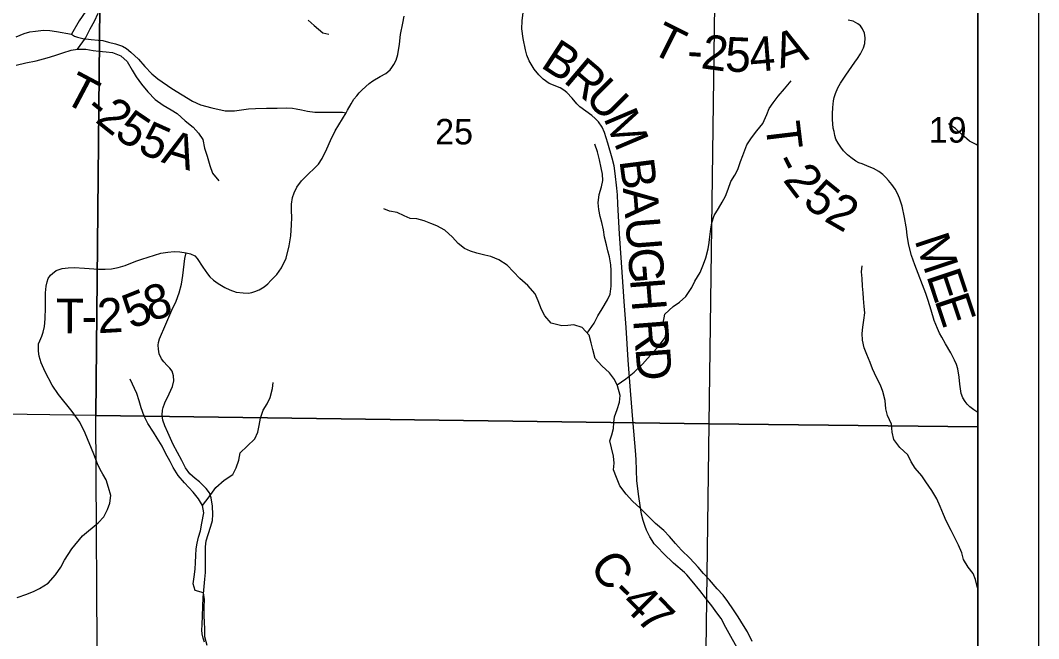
# Model space of a CAD drawing. Extents: x 0 to 34, y -8.9 to 22.
# Drawn here: x 28.944 to 30.617, y 17.37 to 18.385 of the extents above; entities that cross this region are included whole.
import ezdxf

# ---------------------------------------------------------------- set-up
doc = ezdxf.new("R2010")
doc.units = 0
for name, color, linetype in [('GM_X_Corporation', 7, 'Continuous'), ('GM_X_County_Road', 7, 'Continuous'), ('GM_X_County_Road_Text', 7, 'Continuous'), ('GM_X_Minor_River', 7, 'Continuous'), ('GM_X_Section_Text', 7, 'Continuous'), ('GM_X_Township_Road', 7, 'Continuous'), ('GM_X_Township_Road_Text', 7, 'Continuous'), ('SH_Data', 7, 'Continuous')]:
    doc.layers.add(name, color=color, linetype=linetype)

msp = doc.modelspace()

# ---------------------------------------------------------------- linework, layer by layer
at = {"layer": 'GM_X_Corporation'}
msp.add_lwpolyline([(28.3182, 16.8002), (29.5528, 16.7835), (30.4571, 16.7673), (30.5167, 16.7663), (30.5167, 21.4), (23.7167, 21.4)], dxfattribs=at)
for points in [[(30.5167, 16.7663), (30.5167, 21.4), (28.2203, 21.4), (28.2198, 21.3092), (28.2124, 18.7899), (28.2124, 18.7889), (28.2011, 18.1006), (28.201, 18.0921), (28.1882, 17.3108), (28.1928, 16.8054), (28.3182, 16.8002), (29.5528, 16.7835), (30.4571, 16.7673)], [(29.0775, 18.7458), (29.0677, 17.7366), (28.2008, 17.7487), (28.2049, 18.3054), (28.2083, 18.7401)], [(30.0887, 18.7357), (30.0751, 17.7225), (29.0677, 17.7366), (29.0775, 18.7458)], [(30.5167, 17.7179), (30.5167, 18.7296), (30.0887, 18.7357), (30.0751, 17.7225)], [(30.0751, 17.7225), (30.0622, 16.7735), (29.0733, 16.7902), (29.0677, 17.7366)], [(30.5167, 16.7657), (30.5167, 17.7179), (30.0751, 17.7225), (30.0622, 16.7735)]]:
    msp.add_lwpolyline(points, close=True, dxfattribs=at)
at = {"layer": 'GM_X_County_Road'}
msp.add_lwpolyline([(30.1266, 17.3451), (30.1026, 17.3879), (30.095, 17.4027), (30.0894, 17.4102), (30.0852, 17.4163), (30.0796, 17.4237), (30.0756, 17.4292), (30.0694, 17.4369), (30.0599, 17.449), (30.0477, 17.4641), (30.0388, 17.4747), (30.0351, 17.4784), (30.017, 17.494), (30.0002, 17.5097), (29.9911, 17.5195), (29.9853, 17.5258), (29.9817, 17.531), (29.978, 17.5371), (29.9757, 17.5413), (29.9725, 17.548), (29.97, 17.5541), (29.967, 17.5637), (29.9644, 17.5745), (29.962, 17.5883), (29.9598, 17.6032), (29.9565, 17.629), (29.9552, 17.6642), (29.9545, 17.6788), (29.9503, 17.7232), (29.9459, 17.7772), (29.9425, 17.8272), (29.9392, 17.8808), (29.9357, 17.9239), (29.9346, 17.9403), (29.9312, 17.9875), (29.9282, 18.0348), (29.9254, 18.0833), (29.9247, 18.0989), (29.9238, 18.11), (29.9211, 18.134), (29.9192, 18.1467), (29.9162, 18.1589), (29.9091, 18.1836), (29.9035, 18.201), (29.8994, 18.21), (29.8936, 18.2188), (29.8883, 18.2244), (29.8826, 18.2291), (29.8728, 18.2364), (29.8631, 18.2432), (29.858, 18.2485), (29.8502, 18.2578), (29.8416, 18.2669), (29.8365, 18.2706), (29.8304, 18.2745), (29.8126, 18.282), (29.8028, 18.2887), (29.7954, 18.2959), (29.7879, 18.3054), (29.7799, 18.3192), (29.7761, 18.3281), (29.7736, 18.3372), (29.7698, 18.3557), (29.7676, 18.3715), (29.768, 18.3849), (29.7704, 18.4027)], dxfattribs=at)
at = {"layer": 'GM_X_Minor_River'}
for points in [[(29.0376, 18.3379), (29.0506, 18.3563), (29.0584, 18.3716), (29.0654, 18.3842), (29.0717, 18.3972)], [(29.4167, 18.3857), (29.4263, 18.3771), (29.4405, 18.3648), (29.4508, 18.363)], [(28.937, 18.3119), (28.9529, 18.3159), (28.9695, 18.3192), (28.9816, 18.322), (28.9915, 18.3248), (29.0039, 18.3291), (29.0138, 18.3323), (29.0274, 18.3367), (29.0376, 18.3379), (29.0512, 18.3381), (29.0634, 18.336), (29.0729, 18.335), (29.0847, 18.334), (29.0953, 18.3326), (29.1087, 18.3271), (29.119, 18.3181), (29.1272, 18.3034), (29.1338, 18.2929), (29.1427, 18.2804), (29.1531, 18.268), (29.165, 18.2553), (29.1784, 18.2463), (29.1914, 18.2385), (29.2014, 18.2322), (29.2144, 18.2206), (29.2278, 18.2098), (29.2367, 18.2), (29.2433, 18.1895), (29.2461, 18.1755), (29.2508, 18.1622), (29.2552, 18.1471), (29.2592, 18.1342), (29.2696, 18.1218)], [(29.9241, 17.7865), (29.9386, 17.7967), (29.9521, 17.8075), (29.9656, 17.8206), (29.9742, 17.8302), (29.9843, 17.8413), (29.9936, 17.8517), (30.0033, 17.8644), (30.0051, 17.8758), (29.9996, 17.8882), (30.0028, 17.9027), (30.0163, 17.9154), (30.0265, 17.9224), (30.037, 17.9316), (30.047, 17.9466), (30.0518, 17.9569), (30.0607, 17.9714), (30.0659, 17.9852), (30.0699, 17.9955), (30.0735, 18.0099), (30.0753, 18.0206), (30.0767, 18.0301), (30.0784, 18.043), (30.0798, 18.0529), (30.0834, 18.0651), (30.0908, 18.0766), (30.0968, 18.0866), (30.102, 18.0969), (30.1068, 18.108), (30.1111, 18.1209), (30.1178, 18.1309), (30.1223, 18.1404), (30.1266, 18.1534), (30.1307, 18.1637), (30.1373, 18.1809), (30.1447, 18.1927), (30.1537, 18.2042), (30.1638, 18.2161), (30.17, 18.2306), (30.1741, 18.2406), (30.1808, 18.2502), (30.189, 18.2609), (30.1991, 18.2728), (30.2103, 18.2862)], [(30.5167, 18.1801), (30.514, 18.1815), (30.5033, 18.1871), (30.4903, 18.1979), (30.4803, 18.2077), (30.4684, 18.2155)], [(29.8751, 17.8716), (29.8865, 17.8883), (29.8925, 17.9002), (29.8995, 17.9116), (29.9084, 17.9262), (29.9125, 17.9357), (29.9142, 17.9487), (29.9144, 17.9627), (29.9142, 17.9745), (29.9137, 17.984), (29.9117, 17.9968), (29.9089, 18.0067), (29.9065, 18.0169), (29.9037, 18.0294), (29.9016, 18.0411), (29.8992, 18.0536), (29.8964, 18.0635), (29.894, 18.0745), (29.8931, 18.0858), (29.8948, 18.0992), (29.8984, 18.1121), (29.9005, 18.1224), (29.9004, 18.133), (29.898, 18.1432), (29.8952, 18.1565), (29.8919, 18.1697), (29.8876, 18.1822)], [(29.7776, 17.9499), (29.7645, 17.9615), (29.7538, 17.9724), (29.7434, 17.9833), (29.73, 17.9922), (29.7166, 17.9974), (29.7068, 17.9999), (29.6938, 18.0032), (29.6831, 18.0064), (29.6736, 18.0109), (29.6629, 18.0191), (29.6536, 18.0292), (29.6413, 18.0408), (29.628, 18.0479), (29.618, 18.0519), (29.6074, 18.056), (29.5952, 18.0592), (29.5842, 18.0598), (29.5743, 18.0643), (29.5628, 18.0698), (29.5502, 18.0723), (29.5407, 18.0756)], [(30.5167, 17.4524), (30.5164, 17.4532), (30.5128, 17.4669), (30.5089, 17.4767), (30.5008, 17.4872), (30.4934, 17.5), (30.4906, 17.5106), (30.4851, 17.5231), (30.4727, 17.5472), (30.4645, 17.5635), (30.4606, 17.5737), (30.4547, 17.5869), (30.4492, 17.5997), (30.4411, 17.6129), (30.4314, 17.6272), (30.4248, 17.6374), (30.414, 17.6498), (30.4074, 17.6603), (30.4016, 17.672), (30.3889, 17.684), (30.3789, 17.6972), (30.3761, 17.7089), (30.3748, 17.7222), (30.3685, 17.7365), (30.3657, 17.7475), (30.3644, 17.7612), (30.3608, 17.7759), (30.3568, 17.7861), (30.3502, 17.7989), (30.344, 17.8129), (30.34, 17.8235), (30.3342, 17.8367), (30.3299, 17.8473), (30.3274, 17.8602), (30.3269, 17.8712), (30.3279, 17.8814), (30.3296, 17.8932), (30.331, 17.905), (30.3301, 17.9156), (30.3288, 17.9285), (30.3283, 17.938), (30.3274, 17.949), (30.3265, 17.9612), (30.3259, 17.9725), (30.3269, 17.9824)], [(30.1461, 17.3653), (30.1383, 17.3812), (30.1317, 17.3914), (30.1228, 17.4057), (30.1151, 17.4174), (30.1062, 17.4309), (30.0984, 17.4414), (30.0884, 17.4519), (30.0757, 17.4666), (30.0661, 17.4767), (30.0572, 17.4872), (30.0434, 17.5019), (30.0299, 17.515), (30.0203, 17.5259), (30.0103, 17.5375), (30.0007, 17.5476), (29.9872, 17.5592), (29.9753, 17.5712), (29.9622, 17.584), (29.9492, 17.5956), (29.9392, 17.6072), (29.9288, 17.6208), (29.9229, 17.6347), (29.9182, 17.6472), (29.9192, 17.6582), (29.9182, 17.6696), (29.915, 17.6832), (29.9122, 17.695), (29.9155, 17.7045), (29.918, 17.7152), (29.9187, 17.7247), (29.9201, 17.7342), (29.9241, 17.746), (29.9281, 17.7582), (29.9291, 17.7692), (29.9247, 17.7851), (29.92, 17.7953), (29.9115, 17.8062), (29.8992, 17.8178), (29.8881, 17.8298), (29.8845, 17.845), (29.8817, 17.8556), (29.8781, 17.8685), (29.8665, 17.8808), (29.8532, 17.8852), (29.843, 17.8843), (29.8335, 17.8838), (29.816, 17.8882), (29.8056, 17.9002), (29.8001, 17.9107), (29.7942, 17.9247), (29.7895, 17.9364), (29.7776, 17.9499)], [(29.2504, 17.3584), (29.2468, 17.3727), (29.247, 17.386), (29.2465, 17.397), (29.246, 17.4073), (29.2458, 17.421), (29.2464, 17.4339), (29.2447, 17.4452), (29.231, 17.4489), (29.2274, 17.4598), (29.2292, 17.4712), (29.2309, 17.4838), (29.2315, 17.4948), (29.2318, 17.5062), (29.2328, 17.5172), (29.2342, 17.5267), (29.2363, 17.5363), (29.2396, 17.5469), (29.2421, 17.5595), (29.2453, 17.5766), (29.2428, 17.5888), (29.2366, 17.5997), (29.2274, 17.6106), (29.2135, 17.6256), (29.2031, 17.6376), (29.1946, 17.6508), (29.1899, 17.6606), (29.1821, 17.6745), (29.177, 17.6859), (29.1685, 17.699), (29.1623, 17.7088), (29.1534, 17.7235), (29.1472, 17.7352), (29.1421, 17.7492), (29.1389, 17.7602), (29.1353, 17.7723), (29.1244, 17.7961)], [(29.2429, 17.5884), (29.254, 17.6026), (29.2648, 17.6183), (29.2787, 17.6302), (29.2926, 17.6395), (29.2982, 17.6506), (29.3026, 17.6632), (29.3051, 17.675), (29.3163, 17.6862), (29.329, 17.6981), (29.3338, 17.7092), (29.336, 17.7198), (29.3381, 17.732), (29.3428, 17.745), (29.3491, 17.7553), (29.3539, 17.766), (29.3579, 17.7805), (29.3593, 17.7904)]]:
    msp.add_lwpolyline(points, dxfattribs=at)
at = {"layer": 'GM_X_Township_Road'}
for points in [[(29.0514, 18.4006), (29.0404, 18.3848), (29.0279, 18.3626)], [(29.2463, 17.3639), (29.2439, 17.3706), (29.2424, 17.3776), (29.2419, 17.3839), (29.2427, 17.3923), (29.2442, 17.4372), (29.2468, 17.4673), (29.2477, 17.4783), (29.2479, 17.5006), (29.2477, 17.5207), (29.2491, 17.5304), (29.2521, 17.5408), (29.2567, 17.5545), (29.2592, 17.564), (29.2601, 17.5735), (29.2593, 17.5877), (29.257, 17.6009), (29.2544, 17.6093), (29.2492, 17.6167), (29.2438, 17.622), (29.238, 17.6272), (29.2308, 17.633), (29.2223, 17.6407), (29.2152, 17.6503), (29.2091, 17.6626), (29.1949, 17.6889), (29.1858, 17.7084), (29.1811, 17.7195), (29.1781, 17.7289), (29.1765, 17.7371), (29.1771, 17.7449), (29.1784, 17.7496), (29.1809, 17.7572), (29.1884, 17.7719), (29.1939, 17.784), (29.196, 17.7933), (29.1953, 17.8016), (29.1934, 17.809), (29.1895, 17.8143), (29.185, 17.8186), (29.1795, 17.8244), (29.1757, 17.8296), (29.172, 17.8376), (29.1712, 17.8414), (29.1705, 17.8451), (29.1701, 17.8518), (29.1709, 17.8562), (29.1721, 17.8624), (29.1825, 17.8864), (29.1927, 17.9092), (29.1996, 17.9242), (29.2045, 17.938), (29.2085, 17.9519), (29.2109, 17.9662), (29.2138, 17.9941), (29.2163, 18.0038), (29.2233, 18.0021), (29.2302, 17.9984), (29.2344, 17.9941), (29.2436, 17.9799), (29.251, 17.9692), (29.2548, 17.9642), (29.2613, 17.9588), (29.2688, 17.9531), (29.2795, 17.9468), (29.2877, 17.9427), (29.2981, 17.9392), (29.3097, 17.9377), (29.3185, 17.9375), (29.3238, 17.9384), (29.3289, 17.94), (29.3362, 17.9428), (29.3444, 17.9477), (29.3502, 17.9528), (29.3555, 17.9579), (29.3652, 17.9681), (29.373, 17.9789), (29.3806, 17.995), (29.3852, 18.015), (29.3879, 18.0316), (29.3893, 18.0494), (29.3896, 18.0615), (29.3892, 18.0732), (29.3892, 18.0837), (29.391, 18.0945), (29.3934, 18.102), (29.3979, 18.1115), (29.4058, 18.122), (29.4171, 18.1336), (29.4263, 18.1423), (29.4335, 18.1494), (29.4397, 18.1584), (29.4472, 18.1742), (29.4535, 18.188), (29.4612, 18.2039), (29.4792, 18.2338), (29.4811, 18.2382), (29.4872, 18.2486), (29.4918, 18.2558), (29.4967, 18.2617), (29.5004, 18.2664), (29.5045, 18.2706), (29.5111, 18.277), (29.5168, 18.2817), (29.5229, 18.2859), (29.5347, 18.2931), (29.5441, 18.2982), (29.5512, 18.3041), (29.5542, 18.3079), (29.5573, 18.313), (29.561, 18.3201), (29.5637, 18.3293), (29.5667, 18.3466), (29.5684, 18.3621), (29.5719, 18.3807), (29.5744, 18.3921)], [(30.399, 18.0465), (30.3965, 18.0614), (30.3924, 18.0802), (30.388, 18.0935), (30.3847, 18.1013), (30.3809, 18.1081), (30.3757, 18.1156), (30.3702, 18.1225), (30.3657, 18.1271), (30.3607, 18.1321), (30.354, 18.1373), (30.3452, 18.1419), (30.338, 18.145), (30.3267, 18.1496), (30.3215, 18.1515), (30.3163, 18.1544), (30.3079, 18.1601), (30.3027, 18.1643), (30.2963, 18.1711), (30.2918, 18.1769), (30.2873, 18.1836), (30.2837, 18.1904), (30.2819, 18.1962), (30.2806, 18.2029), (30.2792, 18.2085), (30.278, 18.2225), (30.2782, 18.2319), (30.2785, 18.2425), (30.2797, 18.2533), (30.2809, 18.2587), (30.2831, 18.2651), (30.287, 18.2749), (30.2911, 18.2823), (30.2998, 18.2953), (30.3147, 18.3167), (30.319, 18.3227), (30.324, 18.3307), (30.3289, 18.3401), (30.331, 18.3473), (30.3318, 18.3567), (30.3307, 18.3647), (30.3272, 18.3715), (30.3241, 18.3764), (30.3194, 18.38), (30.3117, 18.3839), (30.3036, 18.3858)], [(28.9369, 18.3586), (28.9501, 18.3637), (28.9592, 18.3666), (28.9689, 18.3679), (28.9818, 18.3693), (28.9923, 18.3688), (29.0033, 18.3671), (29.0279, 18.3626)], [(29.0279, 18.3626), (29.0329, 18.3593), (29.0377, 18.3577), (29.0463, 18.3559), (29.0599, 18.3541), (29.0718, 18.353), (29.0794, 18.3523), (29.0885, 18.3499), (29.0998, 18.3469), (29.1116, 18.343), (29.1184, 18.3393), (29.1253, 18.3334), (29.1378, 18.3217), (29.1485, 18.3095), (29.1596, 18.2976), (29.1696, 18.2892), (29.1926, 18.2735), (29.2263, 18.2527), (29.2397, 18.2468), (29.2585, 18.2417), (29.2801, 18.237), (29.2958, 18.237), (29.3183, 18.2402), (29.3303, 18.2405), (29.3483, 18.241), (29.3656, 18.2415), (29.3807, 18.2418), (29.3907, 18.2414), (29.3968, 18.2402), (29.4054, 18.2385), (29.4154, 18.2364), (29.4278, 18.2348), (29.4432, 18.2344), (29.4666, 18.2345), (29.4732, 18.2345), (29.4792, 18.2338)], [(30.5167, 17.7412), (30.5102, 17.7457), (30.5038, 17.7504), (30.4991, 17.7552), (30.4958, 17.7595), (30.492, 17.7654), (30.4896, 17.7723), (30.4871, 17.7876), (30.4863, 17.7996), (30.4837, 17.8128), (30.4815, 17.8203), (30.4785, 17.8272), (30.4724, 17.8394), (30.4636, 17.8543), (30.4578, 17.865), (30.4539, 17.8715), (30.4506, 17.8791), (30.4452, 17.8922), (30.4401, 17.9095), (30.4354, 17.9251), (30.4311, 17.9369), (30.4133, 17.9837), (30.4079, 17.9991), (30.4034, 18.0161), (30.4009, 18.0318), (30.3995, 18.0437), (30.399, 18.0465)], [(28.9737, 17.8539), (28.9755, 17.8588), (28.9791, 17.8667), (28.9814, 17.8734), (28.9832, 17.8825), (28.9847, 17.8954), (28.9848, 17.914), (28.9853, 17.9377), (28.9864, 17.9488), (28.9878, 17.9557), (28.9897, 17.9612), (28.9931, 17.9669), (28.9965, 17.9699), (29.0028, 17.9748), (29.0126, 17.978), (29.0222, 17.9792), (29.0319, 17.9796), (29.049, 17.9786), (29.0721, 17.9767), (29.0831, 17.9767), (29.0934, 17.9771), (29.1045, 17.9794), (29.1158, 17.9828), (29.1337, 17.9899), (29.1432, 17.9934), (29.1639, 17.9998), (29.1744, 18.0029), (29.1863, 18.0049), (29.1964, 18.0059), (29.2057, 18.0054), (29.2163, 18.0038)], [(28.9384, 17.4372), (28.9542, 17.4427), (28.9667, 17.448), (28.975, 17.4523), (28.9822, 17.4564), (28.9892, 17.4611), (29.0013, 17.4744), (29.0101, 17.487), (29.0165, 17.4989), (29.0282, 17.5175), (29.0461, 17.5388), (29.0714, 17.5601), (29.0807, 17.57), (29.0867, 17.5819), (29.0907, 17.5924), (29.0925, 17.6052), (29.0885, 17.618), (29.0845, 17.6307), (29.0791, 17.6399), (29.0751, 17.6478), (29.0706, 17.6572), (29.0646, 17.6728), (29.0505, 17.7074), (29.0414, 17.7252), (29.029, 17.7429), (29.0066, 17.7711), (28.996, 17.7864), (28.9843, 17.8079), (28.9781, 17.8231), (28.9747, 17.8341), (28.9737, 17.842), (28.9737, 17.8539)]]:
    msp.add_lwpolyline(points, dxfattribs=at)
at = {"layer": 'SH_Data'}
for points in [[(23.6167, 21.5), (30.6167, 21.5), (30.6167, 14.5), (23.6167, 14.5)], [(23.7167, 21.4), (30.5167, 21.4), (30.5167, 14.6), (23.7167, 14.6)]]:
    msp.add_lwpolyline(points, close=True, dxfattribs=at)

# ---------------------------------------------------------------- texts
at = {"layer": 'GM_X_County_Road_Text'}
for s, rotation, p in [('B', 326.8382, (29.7966, 18.3096)), ('R', 319.6857, (29.8342, 18.2852)), ('U', 315.0515, (29.8689, 18.2559)), ('M', 292.9632, (29.9011, 18.2253)), ('B', 277.2712, (29.9278, 18.1554)), ('A', 274.5728, (29.9336, 18.1098)), ('U', 274.4415, (29.9376, 18.06)), ('G', 274.4416, (29.9414, 18.0101)), ('H', 274.4433, (29.9453, 17.9603)), ('R', 274.4421, (29.9505, 17.893)), ('D', 274.4416, (29.9542, 17.8465)), ('C', 305.1656, (29.8772, 17.4893)), ('-', 315.9062, (29.9117, 17.4423)), ('4', 315.4305, (29.9283, 17.4262)), ('7', 314.5731, (29.9531, 17.4018))]:
    msp.add_text(s, height=0.0568, rotation=rotation, dxfattribs=at).set_placement(p)
at = {"layer": 'GM_X_Section_Text'}
for s, p in [('25', (29.6252, 18.1817)), ('19', (30.436, 18.1846))]:
    msp.add_text(s, height=0.04186, rotation=0, dxfattribs=at).set_placement(p)
at = {"layer": 'GM_X_Township_Road_Text'}
for s, rotation, p in [('T', 333.3104, (29.9762, 18.334)), ('A', 18.2701, (30.1928, 18.3061)), ('2', 352.154, (30.0604, 18.3071)), ('5', 357.443, (30.1007, 18.3018)), ('4', 4.6041, (30.1435, 18.3003)), ('-', 356.4423, (30.0382, 18.3084)), ('T', 332.1143, (29.0114, 18.2527)), ('-', 321.2829, (29.0466, 18.2344)), ('2', 321.4481, (29.065, 18.2197)), ('5', 325.7646, (29.0961, 18.1951)), ('5', 335.7528, (29.1345, 18.1701)), ('T', 276.8561, (30.1675, 18.2161)), ('A', 343.1356, (29.1739, 18.1529)), ('-', 297.3113, (30.1791, 18.1529)), ('2', 307.2358, (30.1955, 18.1231)), ('5', 320.9595, (30.227, 18.0846)), ('2', 330.1703, (30.2624, 18.0569)), ('M', 288.3369, (30.4124, 18.0247)), ('E', 288.332, (30.4318, 17.9661)), ('8', 17.594, (29.1572, 17.8903)), ('5', 21.5601, (29.1257, 17.8777)), ('E', 288.445, (30.4452, 17.9257)), ('T', 359.49, (29.0016, 17.8718)), ('2', 3.4076, (29.0716, 17.8714)), ('-', 359.8563, (29.0445, 17.8714))]:
    msp.add_text(s, height=0.0568, rotation=rotation, dxfattribs=at).set_placement(p)

doc.saveas('drawing.dxf')
